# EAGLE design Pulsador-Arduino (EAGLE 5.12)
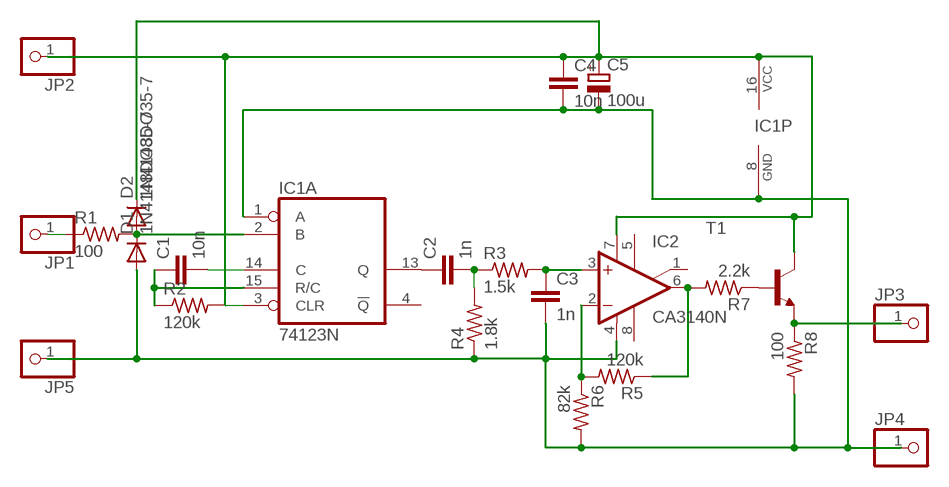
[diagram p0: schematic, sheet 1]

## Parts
C1  10n  C-EU050-024X044  [C050-024X044]
C2  1n  C-EU050-024X044  [C050-024X044]
C3  1n  C-EU050-024X044  [C050-024X044]
C4  10n  C-EU025-025X050  [C025-025X050]
C5  100u  CPOL-EUE3.5-10  [E3,5-10]
D1  1N4148DO35-7  [DO35-7]
D2  1N4148DO35-7  [DO35-7]
IC1  74123N  [DIL16]
IC2  CA3140N  [DIL08]
JP1  PINHD-1X1  [1X01]
JP2  PINHD-1X1  [1X01]
JP3  PINHD-1X1  [1X01]
JP4  PINHD-1X1  [1X01]
JP5  PINHD-1X1  [1X01]
R1  100  R-US_0204/7  [0204/7]
R2  120k  R-US_0204/7  [0204/7]
R3  1.5k  R-US_0204/7  [0204/7]
R4  1.8k  R-US_0204/7  [0204/7]
R5  120k  R-US_0204/7  [0204/7]
R6  82k  R-US_0204/7  [0204/7]
R7  2.2k  R-US_0204/7  [0204/7]
R8  100  R-US_0204/7  [0204/7]
T1  -NPN-TO18-  [TO18-]

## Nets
N$2: C4.1 C5.+ D2.C IC1.3(A:CLR) IC1.16(P:VCC) IC2.7(V+) JP2.1 R2.2 T1.3(C)
N$3: JP3.1 R8.1 T1.1(E)
N$4: C2.2 R3.1 R4.2
N$5: C3.1 IC2.3(+IN) R3.2
N$6: C2.1 IC1.13(A:Q)
N$7: IC2.6(OUT) R5.1 R7.2
N$8: IC2.2(-IN) R5.2 R6.1
N$9: R7.1 T1.2(B)
N$10: D1.C D2.A IC1.2(A:B) R1.2
N$11: JP1.1 R1.1
N$12: C1.2 IC1.14(A:C)
N$13: C1.1 IC1.15(A:R/C) R2.1
N$17: C3.2 C4.2 C5.- D1.A IC1.1(A:A) IC1.8(P:GND) IC2.4(V-) JP4.1 JP5.1 R4.1 R6.2 R8.2
Unconnected: IC1.4(A:!Q) IC1.5(B:Q) IC1.6(B:C) IC1.7(B:R/C) IC1.9(B:A) IC1.10(B:B) IC1.11(B:CLR) IC1.12(B:!Q) IC2.1(ON/CMP) IC2.5(ON) IC2.8(CMP)

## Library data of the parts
C1-C4 = rcl:C-EU: CAPACITOR, European symbol
C5 = rcl:CPOL-EU: POLARIZED CAPACITOR, European symbol
D1 D2 = diode:1N4148: DIODE
IC1 = 74xx-us:74*123: Retriggerable monostable MULTIVIBRATOR
IC2 = linear:CA3140: OP AMP
JP1-JP5 = pinhead:PINHD-1X1: PIN HEADER
R1-R8 = rcl:R-US_: RESISTOR, American symbol
T1 = transistor:*-NPN-: NPN Transistror BF959 corrected 2008.03.06

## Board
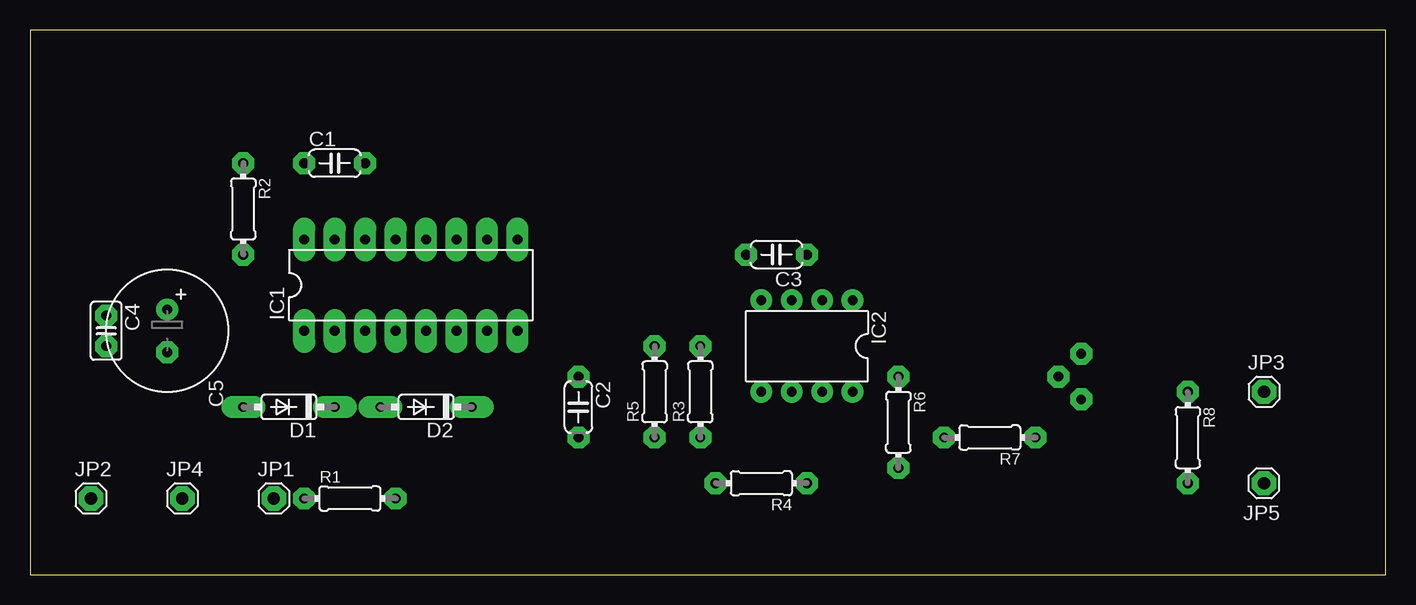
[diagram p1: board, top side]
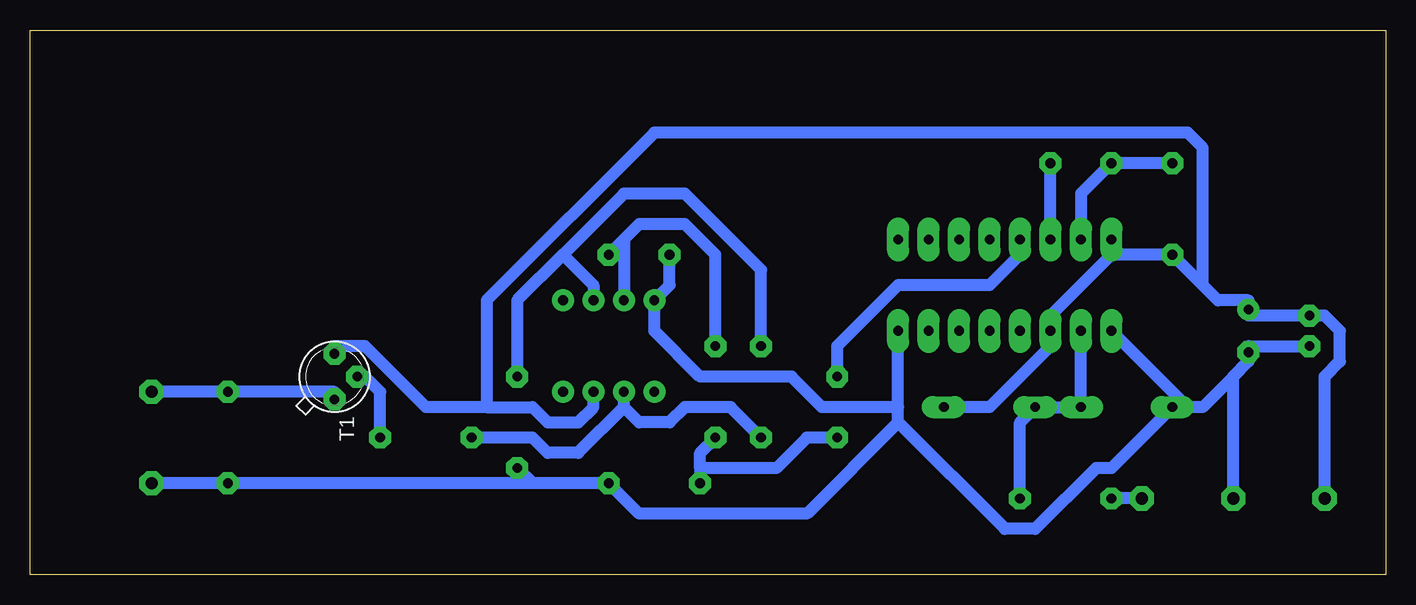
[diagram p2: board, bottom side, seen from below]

Size 113.01 x 45.39 mm. Coordinates in mm from the lower left corner, seen from the top.
Outline: 0,0 113.01,0 113.01,45.39 0,45.39 0,0
Copper layers (1*16): Top 0.035mm / dielectric 1.5mm / Bottom 0.035mm
Design rules "default *": minimum track width 40mil, minimum drill 24mil, track to track 16mil, track to pad 16mil, pad to pad 8mil, via to via 8mil, smd to smd 8mil, copper to edge 40mil, drill to drill 8mil, minimum pad ring 20mil, minimum via ring 8mil, stop-mask expansion 4mil, vias tented up to drill 0mil, thermal gap 10mil

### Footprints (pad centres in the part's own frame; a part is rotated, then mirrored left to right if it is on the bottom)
C050-024X044 = drill 0.813 octagon: 1 -2.54,0; 2 2.54,0
C025-025X050 = drill 0.813 octagon: 1 -1.27,0; 2 1.27,0
E3,5-10 = drill 0.813 pad 1.6 round: + -1.778,0 | drill 0.813 pad 1.6 octagon: - 1.778,0
DO35-7 = drill 0.813 long: A 3.81,0; C -3.81,0
DIL16 = drill 0.813 long: 1 -8.89,-3.81; 2 -6.35,-3.81; 3 -3.81,-3.81; 4 -1.27,-3.81; 5 1.27,-3.81; 6 3.81,-3.81; 7 6.35,-3.81; 8 8.89,-3.81; 9 8.89,3.81; 10 6.35,3.81; 11 3.81,3.81; 12 1.27,3.81; 13 -1.27,3.81; 14 -3.81,3.81; 15 -6.35,3.81; 16 -8.89,3.81
DIL08 = drill 0.813 pad 1.27 round: 1 -3.81,-3.81; 2 -1.27,-3.81; 3 1.27,-3.81; 4 3.81,-3.81; 5 3.81,3.81; 6 1.27,3.81; 7 -1.27,3.81; 8 -3.81,3.81
1X01 = drill 1.016 octagon: 1 0,0
0204/7 = drill 0.813 octagon: 1 -3.81,0; 2 3.81,0
TO18- = drill 0.813 octagon: 1 1.905,0; 2 0,1.905; 3 -1.905,0

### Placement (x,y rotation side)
C1  25.4,34.29 0 top
C2  45.72,13.97 270 top
C3  62.23,26.67 180 top
C4  6.35,20.32 270 top
C5  11.43,20.32 270 top
D1  21.59,13.97 180 top
D2  33.02,13.97 180 top
IC1  31.75,24.13 0 top
IC2  64.77,19.05 180 top
JP1  20.32,6.35 0 top
JP2  5.08,6.35 0 top
JP3  102.87,15.24 0 top
JP4  12.7,6.35 0 top
JP5  102.87,7.62 180 top
R1  26.67,6.35 0 top
R2  17.78,30.48 270 top
R3  55.88,15.24 90 top
R4  60.96,7.62 180 top
R5  52.07,15.24 90 top
R6  72.39,12.7 270 top
R7  80.01,11.43 180 top
R8  96.52,11.43 270 top
T1  87.63,16.51 270 bottom

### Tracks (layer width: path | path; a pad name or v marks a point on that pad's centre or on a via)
N$2
  Bottom 1.016: IC2.7 66.04,13.97 67.31,12.7 69.85,12.7 71.12,13.97 74.93,13.97 | 74.93,13.97 80.01,13.97 85.09,19.05 87.63,19.05 T1.3 | JP2.1 5.08,16.51 3.81,17.78 3.81,20.32 5.08,21.59 C4.1 11.43,21.59 C5.+ 11.43,22.86 13.97,22.86 15.24,24.13 | 22.86,26.67 27.94,21.59 IC1.3 27.94,19.05 33.02,13.97 D2.C | 22.86,26.67 R2.2 15.24,24.13 | 22.86,26.67 IC1.16 | 74.93,13.97 74.93,22.86 60.96,36.83 16.51,36.83 15.24,35.56 15.24,24.13
N$3
  Bottom 1.016: T1.1 87.63,15.24 R8.1 JP3.1
N$4
  Bottom 1.016: 57.15,8.89 57.15,10.16 R3.1 | 57.15,8.89 R4.2 | C2.2 48.26,11.43 50.8,8.89 57.15,8.89
N$5
  Bottom 1.016: R3.2 55.88,26.67 58.42,29.21 62.23,29.21 63.5,27.94 | 63.5,27.94 C3.1 | 63.5,27.94 IC2.3
N$6
  Bottom 1.016: IC1.13 30.48,26.67 33.02,24.13 40.64,24.13 45.72,19.05 C2.1
N$7
  Bottom 1.016: R5.1 54.61,13.97 58.42,13.97 59.69,12.7 62.23,12.7 63.5,13.97 | 63.5,13.97 IC2.6 | R7.2 71.12,11.43 69.85,10.16 67.31,10.16 63.5,13.97
N$8
  Bottom 1.016: R5.2 52.07,25.4 58.42,31.75 63.5,31.75 68.58,26.67 | 68.58,26.67 72.39,22.86 R6.1 | IC2.2 66.04,24.13 68.58,26.67
N$9
  Bottom 1.016: R7.1 83.82,15.24 85.09,16.51 T1.2
N$10
  Bottom 1.016: R1.2 30.48,12.7 D2.A D1.C IC1.2
N$11
  Bottom 1.016: JP1.1 R1.1
N$12
  Bottom 1.016: IC1.14 C1.2
N$13
  Bottom 1.016: R2.1 C1.1 25.4,31.75 IC1.15
N$17
  Bottom 1.016: C4.2 11.43,19.05 C5.- 11.43,17.78 12.7,16.51 | 16.51,13.97 15.24,13.97 12.7,16.51 | 16.51,13.97 IC1.1 | 16.51,13.97 D1.A 22.86,8.89 24.13,8.89 29.21,3.81 31.75,3.81 40.64,12.7 | JP4.1 12.7,16.51 | JP5.1 R8.2 71.12,7.62 | C3.2 59.69,24.13 IC2.4 60.96,20.32 57.15,16.51 49.53,16.51 46.99,13.97 40.64,13.97 | 71.12,7.62 R4.1 62.23,5.08 48.26,5.08 40.64,12.7 | 71.12,7.62 R6.2 | 40.64,12.7 40.64,13.97 | 40.64,13.97 IC1.8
